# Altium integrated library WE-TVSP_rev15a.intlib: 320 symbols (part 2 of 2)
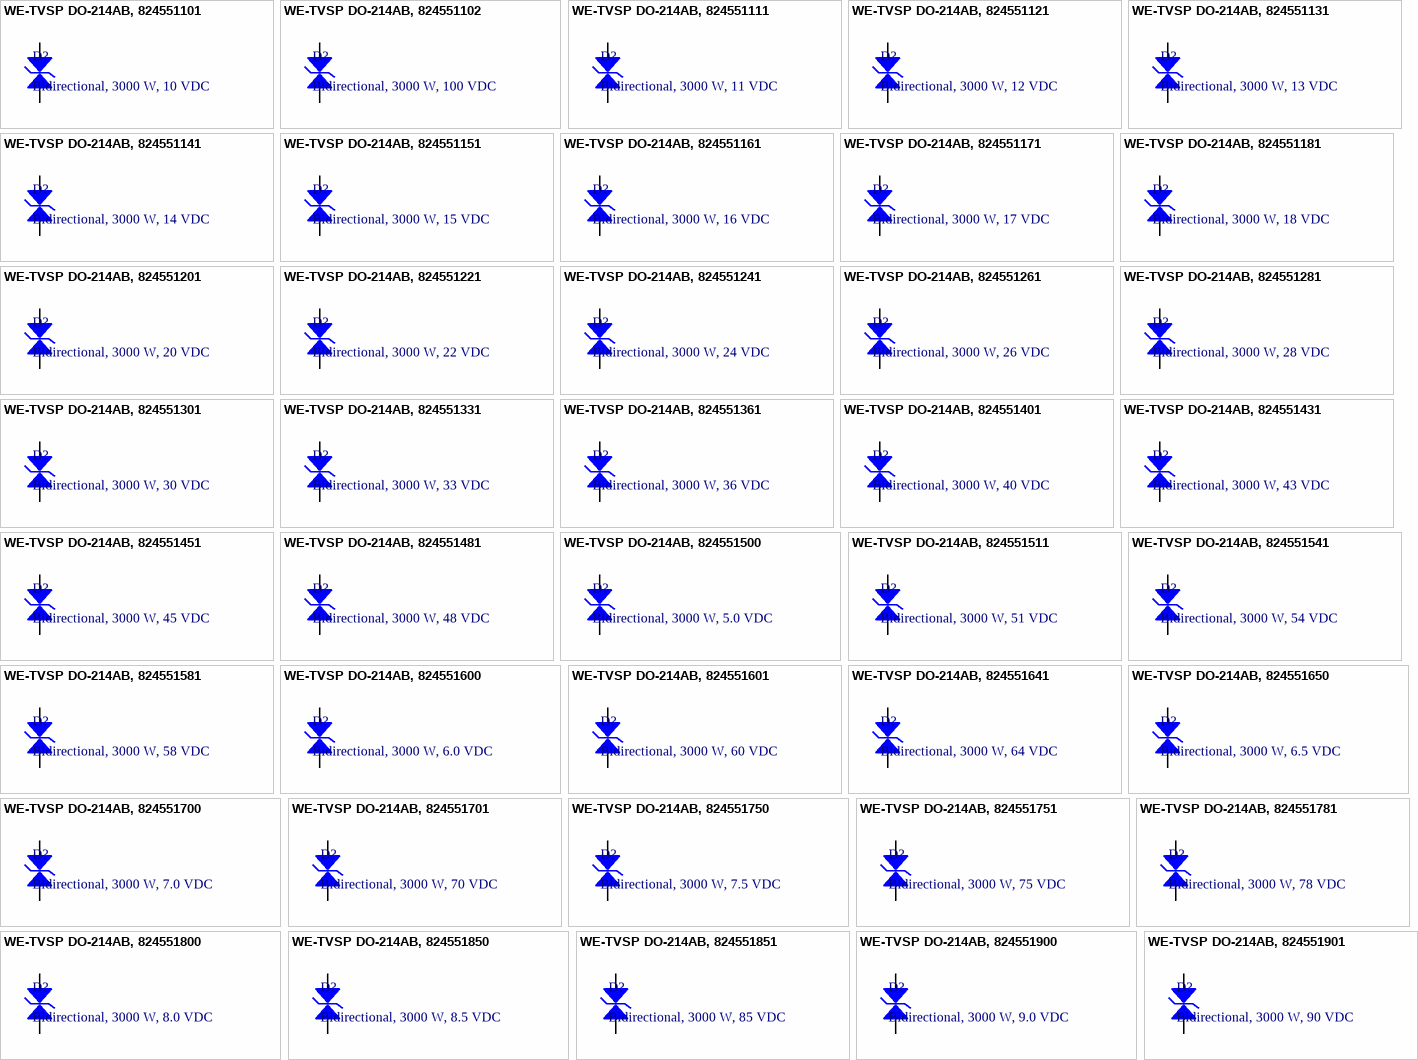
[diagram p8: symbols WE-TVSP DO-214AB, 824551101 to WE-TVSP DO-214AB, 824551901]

## WE-TVSP DO-214AB, 824551171
designator D?, comment Bidirectional, 3000 W, 17 VDC
WE-TVSP Power TVS Diode, bidirectional, 3000 W, 17 VDC; partNo: 824551171; Manufacturer: Wurth Elektronik
footprint DO-214AB_Bidirectional
pins: 1, 2

## WE-TVSP DO-214AB, 824551181
designator D?, comment Bidirectional, 3000 W, 18 VDC
WE-TVSP Power TVS Diode, bidirectional, 3000 W, 18 VDC; partNo: 824551181; Manufacturer: Wurth Elektronik
footprint DO-214AB_Bidirectional
pins: 1, 2

## WE-TVSP DO-214AB, 824551201
designator D?, comment Bidirectional, 3000 W, 20 VDC
WE-TVSP Power TVS Diode, bidirectional, 3000 W, 20 VDC; partNo: 824551201; Manufacturer: Wurth Elektronik
footprint DO-214AB_Bidirectional
pins: 1, 2

## WE-TVSP DO-214AB, 824551221
designator D?, comment Bidirectional, 3000 W, 22 VDC
WE-TVSP Power TVS Diode, bidirectional, 3000 W, 22 VDC; partNo: 824551221; Manufacturer: Wurth Elektronik
footprint DO-214AB_Bidirectional
pins: 1, 2

## WE-TVSP DO-214AB, 824551241
designator D?, comment Bidirectional, 3000 W, 24 VDC
WE-TVSP Power TVS Diode, bidirectional, 3000 W, 24 VDC; partNo: 824551241; Manufacturer: Wurth Elektronik
footprint DO-214AB_Bidirectional
pins: 1, 2

## WE-TVSP DO-214AB, 824551261
designator D?, comment Bidirectional, 3000 W, 26 VDC
WE-TVSP Power TVS Diode, bidirectional, 3000 W, 26 VDC; partNo: 824551261; Manufacturer: Wurth Elektronik
footprint DO-214AB_Bidirectional
pins: 1, 2

## WE-TVSP DO-214AB, 824551281
designator D?, comment Bidirectional, 3000 W, 28 VDC
WE-TVSP Power TVS Diode, bidirectional, 3000 W, 28 VDC; partNo: 824551281; Manufacturer: Wurth Elektronik
footprint DO-214AB_Bidirectional
pins: 1, 2

## WE-TVSP DO-214AB, 824551301
designator D?, comment Bidirectional, 3000 W, 30 VDC
WE-TVSP Power TVS Diode, bidirectional, 3000 W, 30 VDC; partNo: 824551301; Manufacturer: Wurth Elektronik
footprint DO-214AB_Bidirectional
pins: 1, 2

## WE-TVSP DO-214AB, 824551331
designator D?, comment Bidirectional, 3000 W, 33 VDC
WE-TVSP Power TVS Diode, bidirectional, 3000 W, 33 VDC; partNo: 824551331; Manufacturer: Wurth Elektronik
footprint DO-214AB_Bidirectional
pins: 1, 2

## WE-TVSP DO-214AB, 824551361
designator D?, comment Bidirectional, 3000 W, 36 VDC
WE-TVSP Power TVS Diode, bidirectional, 3000 W, 36 VDC; partNo: 824551361; Manufacturer: Wurth Elektronik
footprint DO-214AB_Bidirectional
pins: 1, 2

## WE-TVSP DO-214AB, 824551401
designator D?, comment Bidirectional, 3000 W, 40 VDC
WE-TVSP Power TVS Diode, bidirectional, 3000 W, 40 VDC; partNo: 824551401; Manufacturer: Wurth Elektronik
footprint DO-214AB_Bidirectional
pins: 1, 2

## WE-TVSP DO-214AB, 824551431
designator D?, comment Bidirectional, 3000 W, 43 VDC
WE-TVSP Power TVS Diode, bidirectional, 3000 W, 43 VDC; partNo: 824551431; Manufacturer: Wurth Elektronik
footprint DO-214AB_Bidirectional
pins: 1, 2

## WE-TVSP DO-214AB, 824551451
designator D?, comment Bidirectional, 3000 W, 45 VDC
WE-TVSP Power TVS Diode, bidirectional, 3000 W, 45 VDC; partNo: 824551451; Manufacturer: Wurth Elektronik
footprint DO-214AB_Bidirectional
pins: 1, 2

## WE-TVSP DO-214AB, 824551481
designator D?, comment Bidirectional, 3000 W, 48 VDC
WE-TVSP Power TVS Diode, bidirectional, 3000 W, 48 VDC; partNo: 824551481; Manufacturer: Wurth Elektronik
footprint DO-214AB_Bidirectional
pins: 1, 2

## WE-TVSP DO-214AB, 824551500
designator D?, comment Bidirectional, 3000 W, 5.0 VDC
WE-TVSP Power TVS Diode, bidirectional, 3000 W, 5.0 VDC; partNo: 824551500; Manufacturer: Wurth Elektronik
footprint DO-214AB_Bidirectional
pins: 1, 2

## WE-TVSP DO-214AB, 824551511
designator D?, comment Bidirectional, 3000 W, 51 VDC
WE-TVSP Power TVS Diode, bidirectional, 3000 W, 51 VDC; partNo: 824551511; Manufacturer: Wurth Elektronik
footprint DO-214AB_Bidirectional
pins: 1, 2

## WE-TVSP DO-214AB, 824551541
designator D?, comment Bidirectional, 3000 W, 54 VDC
WE-TVSP Power TVS Diode, bidirectional, 3000 W, 54 VDC; partNo: 824551541; Manufacturer: Wurth Elektronik
footprint DO-214AB_Bidirectional
pins: 1, 2

## WE-TVSP DO-214AB, 824551581
designator D?, comment Bidirectional, 3000 W, 58 VDC
WE-TVSP Power TVS Diode, bidirectional, 3000 W, 58 VDC; partNo: 824551581; Manufacturer: Wurth Elektronik
footprint DO-214AB_Bidirectional
pins: 1, 2

## WE-TVSP DO-214AB, 824551600
designator D?, comment Bidirectional, 3000 W, 6.0 VDC
WE-TVSP Power TVS Diode, bidirectional, 3000 W, 6.0 VDC; partNo: 824551600; Manufacturer: Wurth Elektronik
footprint DO-214AB_Bidirectional
pins: 1, 2

## WE-TVSP DO-214AB, 824551601
designator D?, comment Bidirectional, 3000 W, 60 VDC
WE-TVSP Power TVS Diode, bidirectional, 3000 W, 60 VDC; partNo: 824551601; Manufacturer: Wurth Elektronik
footprint DO-214AB_Bidirectional
pins: 1, 2

## WE-TVSP DO-214AB, 824551641
designator D?, comment Bidirectional, 3000 W, 64 VDC
WE-TVSP Power TVS Diode, bidirectional, 3000 W, 64 VDC; partNo: 824551641; Manufacturer: Wurth Elektronik
footprint DO-214AB_Bidirectional
pins: 1, 2

## WE-TVSP DO-214AB, 824551650
designator D?, comment Bidirectional, 3000 W, 6.5 VDC
WE-TVSP Power TVS Diode, bidirectional, 3000 W, 6.5 VDC; partNo: 824551650; Manufacturer: Wurth Elektronik
footprint DO-214AB_Bidirectional
pins: 1, 2

## WE-TVSP DO-214AB, 824551700
designator D?, comment Bidirectional, 3000 W, 7.0 VDC
WE-TVSP Power TVS Diode, bidirectional, 3000 W, 7.0 VDC; partNo: 824551700; Manufacturer: Wurth Elektronik
footprint DO-214AB_Bidirectional
pins: 1, 2

## WE-TVSP DO-214AB, 824551701
designator D?, comment Bidirectional, 3000 W, 70 VDC
WE-TVSP Power TVS Diode, bidirectional, 3000 W, 70 VDC; partNo: 824551701; Manufacturer: Wurth Elektronik
footprint DO-214AB_Bidirectional
pins: 1, 2

## WE-TVSP DO-214AB, 824551750
designator D?, comment Bidirectional, 3000 W, 7.5 VDC
WE-TVSP Power TVS Diode, bidirectional, 3000 W, 7.5 VDC; partNo: 824551750; Manufacturer: Wurth Elektronik
footprint DO-214AB_Bidirectional
pins: 1, 2

## WE-TVSP DO-214AB, 824551751
designator D?, comment Bidirectional, 3000 W, 75 VDC
WE-TVSP Power TVS Diode, bidirectional, 3000 W, 75 VDC; partNo: 824551751; Manufacturer: Wurth Elektronik
footprint DO-214AB_Bidirectional
pins: 1, 2

## WE-TVSP DO-214AB, 824551781
designator D?, comment Bidirectional, 3000 W, 78 VDC
WE-TVSP Power TVS Diode, bidirectional, 3000 W, 78 VDC; partNo: 824551781; Manufacturer: Wurth Elektronik
footprint DO-214AB_Bidirectional
pins: 1, 2

## WE-TVSP DO-214AB, 824551800
designator D?, comment Bidirectional, 3000 W, 8.0 VDC
WE-TVSP Power TVS Diode, bidirectional, 3000 W, 8.0 VDC; partNo: 824551800; Manufacturer: Wurth Elektronik
footprint DO-214AB_Bidirectional
pins: 1, 2

## WE-TVSP DO-214AB, 824551850
designator D?, comment Bidirectional, 3000 W, 8.5 VDC
WE-TVSP Power TVS Diode, bidirectional, 3000 W, 8.5 VDC; partNo: 824551850; Manufacturer: Wurth Elektronik
footprint DO-214AB_Bidirectional
pins: 1, 2

## WE-TVSP DO-214AB, 824551851
designator D?, comment Bidirectional, 3000 W, 85 VDC
WE-TVSP Power TVS Diode, bidirectional, 3000 W, 85 VDC; partNo: 824551851; Manufacturer: Wurth Elektronik
footprint DO-214AB_Bidirectional
pins: 1, 2

## WE-TVSP DO-214AB, 824551900
designator D?, comment Bidirectional, 3000 W, 9.0 VDC
WE-TVSP Power TVS Diode, bidirectional, 3000 W, 9.0 VDC; partNo: 824551900; Manufacturer: Wurth Elektronik
footprint DO-214AB_Bidirectional
pins: 1, 2

## WE-TVSP DO-214AB, 824551901
designator D?, comment Bidirectional, 3000 W, 90 VDC
WE-TVSP Power TVS Diode, bidirectional, 3000 W, 90 VDC; partNo: 824551901; Manufacturer: Wurth Elektronik
footprint DO-214AB_Bidirectional
pins: 1, 2


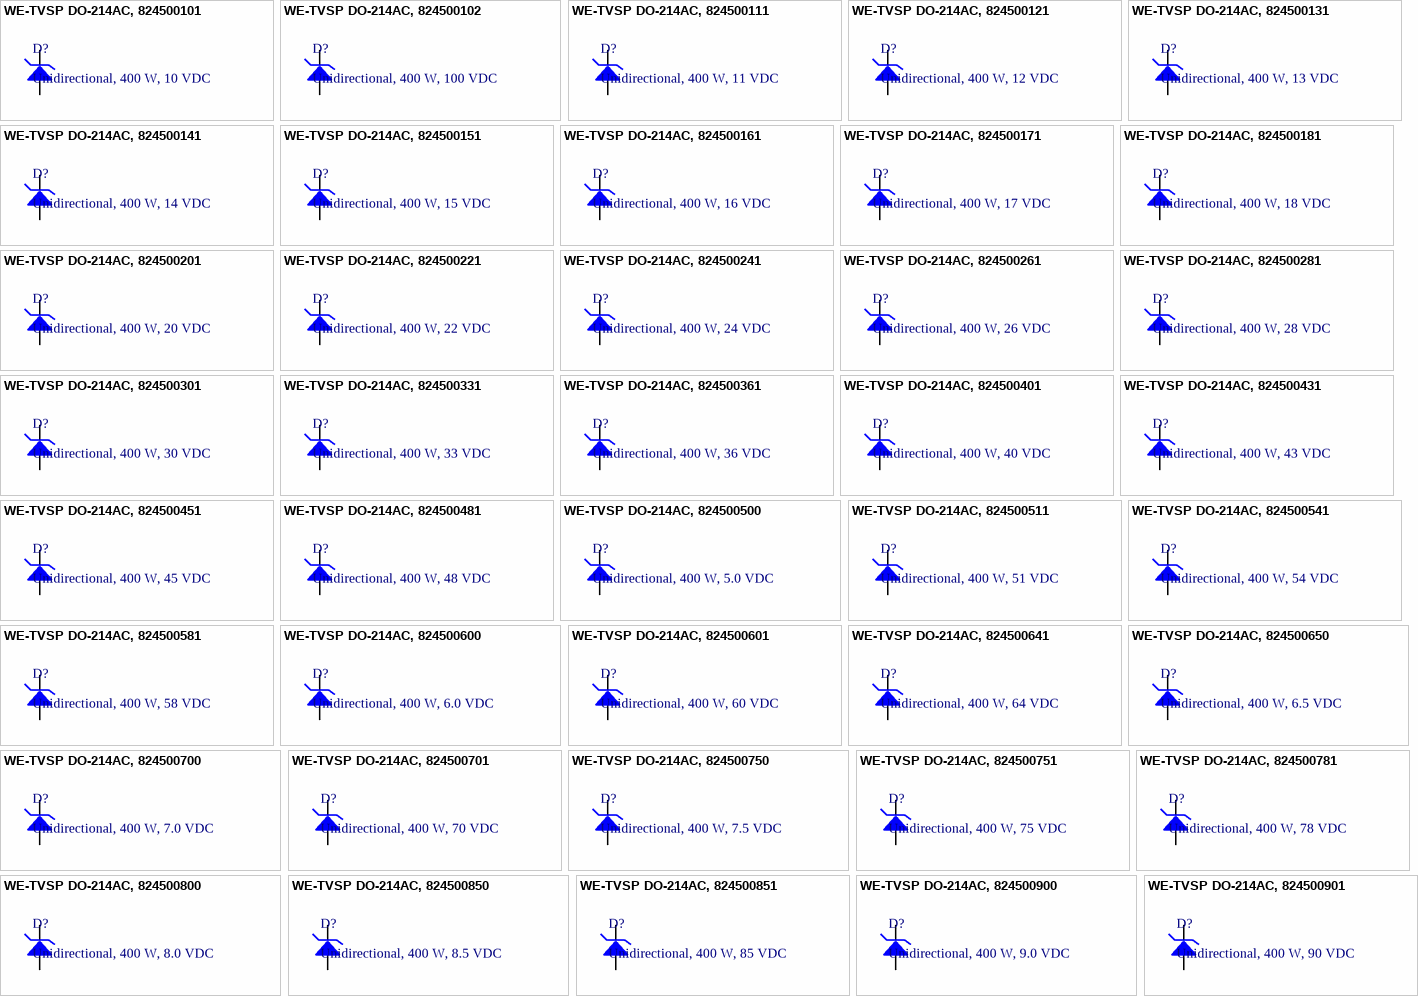
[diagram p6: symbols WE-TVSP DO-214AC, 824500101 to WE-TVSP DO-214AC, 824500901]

## WE-TVSP DO-214AC, 824500101
designator D?, comment Unidirectional, 400 W, 10 VDC
WE-TVSP Power TVS Diode, Unidirectional, 400 W, 10 VDC; partNo: 824500101; Manufacturer: Wurth Elektronik
footprint DO-214AC_Unidirectional
pins: 1, 2

## WE-TVSP DO-214AC, 824500102
designator D?, comment Unidirectional, 400 W, 100 VDC
WE-TVSP Power TVS Diode, Unidirectional, 400 W, 100 VDC; partNo: 824500102; Manufacturer: Wurth Elektronik
footprint DO-214AC_Unidirectional
pins: 1, 2

## WE-TVSP DO-214AC, 824500111
designator D?, comment Unidirectional, 400 W, 11 VDC
WE-TVSP Power TVS Diode, Unidirectional, 400 W, 11 VDC; partNo: 824500111; Manufacturer: Wurth Elektronik
footprint DO-214AC_Unidirectional
pins: 1, 2

## WE-TVSP DO-214AC, 824500121
designator D?, comment Unidirectional, 400 W, 12 VDC
WE-TVSP Power TVS Diode, Unidirectional, 400 W, 12 VDC; partNo: 824500121; Manufacturer: Wurth Elektronik
footprint DO-214AC_Unidirectional
pins: 1, 2

## WE-TVSP DO-214AC, 824500131
designator D?, comment Unidirectional, 400 W, 13 VDC
WE-TVSP Power TVS Diode, Unidirectional, 400 W, 13 VDC; partNo: 824500131; Manufacturer: Wurth Elektronik
footprint DO-214AC_Unidirectional
pins: 1, 2

## WE-TVSP DO-214AC, 824500141
designator D?, comment Unidirectional, 400 W, 14 VDC
WE-TVSP Power TVS Diode, Unidirectional, 400 W, 14 VDC; partNo: 824500141; Manufacturer: Wurth Elektronik
footprint DO-214AC_Unidirectional
pins: 1, 2

## WE-TVSP DO-214AC, 824500151
designator D?, comment Unidirectional, 400 W, 15 VDC
WE-TVSP Power TVS Diode, Unidirectional, 400 W, 15 VDC; partNo: 824500151; Manufacturer: Wurth Elektronik
footprint DO-214AC_Unidirectional
pins: 1, 2

## WE-TVSP DO-214AC, 824500161
designator D?, comment Unidirectional, 400 W, 16 VDC
WE-TVSP Power TVS Diode, Unidirectional, 400 W, 16 VDC; partNo: 824500161; Manufacturer: Wurth Elektronik
footprint DO-214AC_Unidirectional
pins: 1, 2

## WE-TVSP DO-214AC, 824500171
designator D?, comment Unidirectional, 400 W, 17 VDC
WE-TVSP Power TVS Diode, Unidirectional, 400 W, 17 VDC; partNo: 824500171; Manufacturer: Wurth Elektronik
footprint DO-214AC_Unidirectional
pins: 1, 2

## WE-TVSP DO-214AC, 824500181
designator D?, comment Unidirectional, 400 W, 18 VDC
WE-TVSP Power TVS Diode, Unidirectional, 400 W, 18 VDC; partNo: 824500181; Manufacturer: Wurth Elektronik
footprint DO-214AC_Unidirectional
pins: 1, 2

## WE-TVSP DO-214AC, 824500201
designator D?, comment Unidirectional, 400 W, 20 VDC
WE-TVSP Power TVS Diode, Unidirectional, 400 W, 20 VDC; partNo: 824500201; Manufacturer: Wurth Elektronik
footprint DO-214AC_Unidirectional
pins: 1, 2

## WE-TVSP DO-214AC, 824500221
designator D?, comment Unidirectional, 400 W, 22 VDC
WE-TVSP Power TVS Diode, Unidirectional, 400 W, 22 VDC; partNo: 824500221; Manufacturer: Wurth Elektronik
footprint DO-214AC_Unidirectional
pins: 1, 2

## WE-TVSP DO-214AC, 824500241
designator D?, comment Unidirectional, 400 W, 24 VDC
WE-TVSP Power TVS Diode, Unidirectional, 400 W, 24 VDC; partNo: 824500241; Manufacturer: Wurth Elektronik
footprint DO-214AC_Unidirectional
pins: 1, 2

## WE-TVSP DO-214AC, 824500261
designator D?, comment Unidirectional, 400 W, 26 VDC
WE-TVSP Power TVS Diode, Unidirectional, 400 W, 26 VDC; partNo: 824500261; Manufacturer: Wurth Elektronik
footprint DO-214AC_Unidirectional
pins: 1, 2

## WE-TVSP DO-214AC, 824500281
designator D?, comment Unidirectional, 400 W, 28 VDC
WE-TVSP Power TVS Diode, Unidirectional, 400 W, 28 VDC; partNo: 824500281; Manufacturer: Wurth Elektronik
footprint DO-214AC_Unidirectional
pins: 1, 2

## WE-TVSP DO-214AC, 824500301
designator D?, comment Unidirectional, 400 W, 30 VDC
WE-TVSP Power TVS Diode, Unidirectional, 400 W, 30 VDC; partNo: 824500301; Manufacturer: Wurth Elektronik
footprint DO-214AC_Unidirectional
pins: 1, 2

## WE-TVSP DO-214AC, 824500331
designator D?, comment Unidirectional, 400 W, 33 VDC
WE-TVSP Power TVS Diode, Unidirectional, 400 W, 33 VDC; partNo: 824500331; Manufacturer: Wurth Elektronik
footprint DO-214AC_Unidirectional
pins: 1, 2

## WE-TVSP DO-214AC, 824500361
designator D?, comment Unidirectional, 400 W, 36 VDC
WE-TVSP Power TVS Diode, Unidirectional, 400 W, 36 VDC; partNo: 824500361; Manufacturer: Wurth Elektronik
footprint DO-214AC_Unidirectional
pins: 1, 2

## WE-TVSP DO-214AC, 824500401
designator D?, comment Unidirectional, 400 W, 40 VDC
WE-TVSP Power TVS Diode, Unidirectional, 400 W, 40 VDC; partNo: 824500401; Manufacturer: Wurth Elektronik
footprint DO-214AC_Unidirectional
pins: 1, 2

## WE-TVSP DO-214AC, 824500431
designator D?, comment Unidirectional, 400 W, 43 VDC
WE-TVSP Power TVS Diode, Unidirectional, 400 W, 43 VDC; partNo: 824500431; Manufacturer: Wurth Elektronik
footprint DO-214AC_Unidirectional
pins: 1, 2

## WE-TVSP DO-214AC, 824500451
designator D?, comment Unidirectional, 400 W, 45 VDC
WE-TVSP Power TVS Diode, Unidirectional, 400 W, 45 VDC; partNo: 824500451; Manufacturer: Wurth Elektronik
footprint DO-214AC_Unidirectional
pins: 1, 2

## WE-TVSP DO-214AC, 824500481
designator D?, comment Unidirectional, 400 W, 48 VDC
WE-TVSP Power TVS Diode, Unidirectional, 400 W, 48 VDC; partNo: 824500481; Manufacturer: Wurth Elektronik
footprint DO-214AC_Unidirectional
pins: 1, 2

## WE-TVSP DO-214AC, 824500500
designator D?, comment Unidirectional, 400 W, 5.0 VDC
WE-TVSP Power TVS Diode, Unidirectional, 400 W, 5.0 VDC; partNo: 824500500; Manufacturer: Wurth Elektronik
footprint DO-214AC_Unidirectional
pins: 1, 2

## WE-TVSP DO-214AC, 824500511
designator D?, comment Unidirectional, 400 W, 51 VDC
WE-TVSP Power TVS Diode, Unidirectional, 400 W, 51 VDC; partNo: 824500511; Manufacturer: Wurth Elektronik
footprint DO-214AC_Unidirectional
pins: 1, 2

## WE-TVSP DO-214AC, 824500541
designator D?, comment Unidirectional, 400 W, 54 VDC
WE-TVSP Power TVS Diode, Unidirectional, 400 W, 54 VDC; partNo: 824500541; Manufacturer: Wurth Elektronik
footprint DO-214AC_Unidirectional
pins: 1, 2

## WE-TVSP DO-214AC, 824500581
designator D?, comment Unidirectional, 400 W, 58 VDC
WE-TVSP Power TVS Diode, Unidirectional, 400 W, 58 VDC; partNo: 824500581; Manufacturer: Wurth Elektronik
footprint DO-214AC_Unidirectional
pins: 1, 2

## WE-TVSP DO-214AC, 824500600
designator D?, comment Unidirectional, 400 W, 6.0 VDC
WE-TVSP Power TVS Diode, Unidirectional, 400 W, 6.0 VDC; partNo: 824500600; Manufacturer: Wurth Elektronik
footprint DO-214AC_Unidirectional
pins: 1, 2

## WE-TVSP DO-214AC, 824500601
designator D?, comment Unidirectional, 400 W, 60 VDC
WE-TVSP Power TVS Diode, Unidirectional, 400 W, 60 VDC; partNo: 824500601; Manufacturer: Wurth Elektronik
footprint DO-214AC_Unidirectional
pins: 1, 2

## WE-TVSP DO-214AC, 824500641
designator D?, comment Unidirectional, 400 W, 64 VDC
WE-TVSP Power TVS Diode, Unidirectional, 400 W, 64 VDC; partNo: 824500641; Manufacturer: Wurth Elektronik
footprint DO-214AC_Unidirectional
pins: 1, 2

## WE-TVSP DO-214AC, 824500650
designator D?, comment Unidirectional, 400 W, 6.5 VDC
WE-TVSP Power TVS Diode, Unidirectional, 400 W, 6.5 VDC; partNo: 824500650; Manufacturer: Wurth Elektronik
footprint DO-214AC_Unidirectional
pins: 1, 2

## WE-TVSP DO-214AC, 824500700
designator D?, comment Unidirectional, 400 W, 7.0 VDC
WE-TVSP Power TVS Diode, Unidirectional, 400 W, 7.0 VDC; partNo: 824500700; Manufacturer: Wurth Elektronik
footprint DO-214AC_Unidirectional
pins: 1, 2

## WE-TVSP DO-214AC, 824500701
designator D?, comment Unidirectional, 400 W, 70 VDC
WE-TVSP Power TVS Diode, Unidirectional, 400 W, 70 VDC; partNo: 824500701; Manufacturer: Wurth Elektronik
footprint DO-214AC_Unidirectional
pins: 1, 2

## WE-TVSP DO-214AC, 824500750
designator D?, comment Unidirectional, 400 W, 7.5 VDC
WE-TVSP Power TVS Diode, Unidirectional, 400 W, 7.5 VDC; partNo: 824500750; Manufacturer: Wurth Elektronik
footprint DO-214AC_Unidirectional
pins: 1, 2

## WE-TVSP DO-214AC, 824500751
designator D?, comment Unidirectional, 400 W, 75 VDC
WE-TVSP Power TVS Diode, Unidirectional, 400 W, 75 VDC; partNo: 824500751; Manufacturer: Wurth Elektronik
footprint DO-214AC_Unidirectional
pins: 1, 2

## WE-TVSP DO-214AC, 824500781
designator D?, comment Unidirectional, 400 W, 78 VDC
WE-TVSP Power TVS Diode, Unidirectional, 400 W, 78 VDC; partNo: 824500781; Manufacturer: Wurth Elektronik
footprint DO-214AC_Unidirectional
pins: 1, 2

## WE-TVSP DO-214AC, 824500800
designator D?, comment Unidirectional, 400 W, 8.0 VDC
WE-TVSP Power TVS Diode, Unidirectional, 400 W, 8.0 VDC; partNo: 824500800; Manufacturer: Wurth Elektronik
footprint DO-214AC_Unidirectional
pins: 1, 2

## WE-TVSP DO-214AC, 824500850
designator D?, comment Unidirectional, 400 W, 8.5 VDC
WE-TVSP Power TVS Diode, Unidirectional, 400 W, 8.5 VDC; partNo: 824500850; Manufacturer: Wurth Elektronik
footprint DO-214AC_Unidirectional
pins: 1, 2

## WE-TVSP DO-214AC, 824500851
designator D?, comment Unidirectional, 400 W, 85 VDC
WE-TVSP Power TVS Diode, Unidirectional, 400 W, 85 VDC; partNo: 824500851; Manufacturer: Wurth Elektronik
footprint DO-214AC_Unidirectional
pins: 1, 2

## WE-TVSP DO-214AC, 824500900
designator D?, comment Unidirectional, 400 W, 9.0 VDC
WE-TVSP Power TVS Diode, Unidirectional, 400 W, 9.0 VDC; partNo: 824500900; Manufacturer: Wurth Elektronik
footprint DO-214AC_Unidirectional
pins: 1, 2

## WE-TVSP DO-214AC, 824500901
designator D?, comment Unidirectional, 400 W, 90 VDC
WE-TVSP Power TVS Diode, Unidirectional, 400 W, 90 VDC; partNo: 824500901; Manufacturer: Wurth Elektronik
footprint DO-214AC_Unidirectional
pins: 1, 2


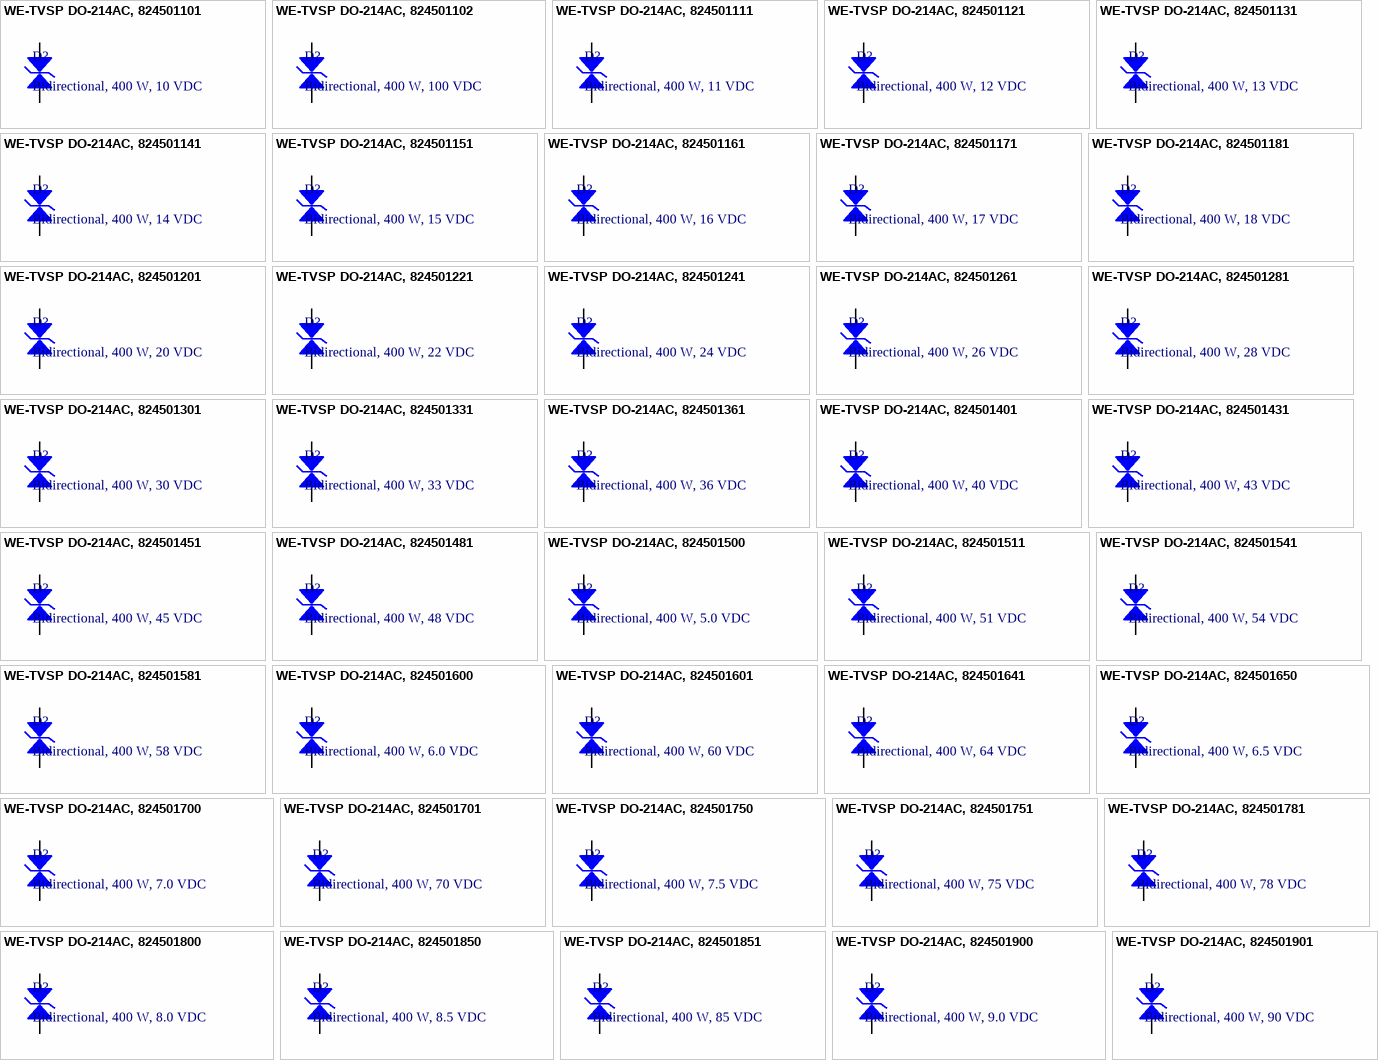
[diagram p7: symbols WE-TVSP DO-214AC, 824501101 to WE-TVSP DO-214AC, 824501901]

## WE-TVSP DO-214AC, 824501101
designator D?, comment Bidirectional, 400 W, 10 VDC
WE-TVSP Power TVS Diode, bidirectional, 400 W, 10 VDC; partNo: 824501101; Manufacturer: Wurth Elektronik
footprint DO-214AC_Bidirectional
pins: 1, 2

## WE-TVSP DO-214AC, 824501102
designator D?, comment Bidirectional, 400 W, 100 VDC
WE-TVSP Power TVS Diode, bidirectional, 400 W, 100 VDC; partNo: 824501102; Manufacturer: Wurth Elektronik
footprint DO-214AC_Bidirectional
pins: 1, 2

## WE-TVSP DO-214AC, 824501111
designator D?, comment Bidirectional, 400 W, 11 VDC
WE-TVSP Power TVS Diode, bidirectional, 400 W, 11 VDC; partNo: 824501111; Manufacturer: Wurth Elektronik
footprint DO-214AC_Bidirectional
pins: 1, 2

## WE-TVSP DO-214AC, 824501121
designator D?, comment Bidirectional, 400 W, 12 VDC
WE-TVSP Power TVS Diode, bidirectional, 400 W, 12 VDC; partNo: 824501121; Manufacturer: Wurth Elektronik
footprint DO-214AC_Bidirectional
pins: 1, 2

## WE-TVSP DO-214AC, 824501131
designator D?, comment Bidirectional, 400 W, 13 VDC
WE-TVSP Power TVS Diode, bidirectional, 400 W, 13 VDC; partNo: 824501131; Manufacturer: Wurth Elektronik
footprint DO-214AC_Bidirectional
pins: 1, 2

## WE-TVSP DO-214AC, 824501141
designator D?, comment Bidirectional, 400 W, 14 VDC
WE-TVSP Power TVS Diode, bidirectional, 400 W, 14 VDC; partNo: 824501141; Manufacturer: Wurth Elektronik
footprint DO-214AC_Bidirectional
pins: 1, 2

## WE-TVSP DO-214AC, 824501151
designator D?, comment Bidirectional, 400 W, 15 VDC
WE-TVSP Power TVS Diode, bidirectional, 400 W, 15 VDC; partNo: 824501151; Manufacturer: Wurth Elektronik
footprint DO-214AC_Bidirectional
pins: 1, 2

## WE-TVSP DO-214AC, 824501161
designator D?, comment Bidirectional, 400 W, 16 VDC
WE-TVSP Power TVS Diode, bidirectional, 400 W, 16 VDC; partNo: 824501161; Manufacturer: Wurth Elektronik
footprint DO-214AC_Bidirectional
pins: 1, 2

## WE-TVSP DO-214AC, 824501171
designator D?, comment Bidirectional, 400 W, 17 VDC
WE-TVSP Power TVS Diode, bidirectional, 400 W, 17 VDC; partNo: 824501171; Manufacturer: Wurth Elektronik
footprint DO-214AC_Bidirectional
pins: 1, 2

## WE-TVSP DO-214AC, 824501181
designator D?, comment Bidirectional, 400 W, 18 VDC
WE-TVSP Power TVS Diode, bidirectional, 400 W, 18 VDC; partNo: 824501181; Manufacturer: Wurth Elektronik
footprint DO-214AC_Bidirectional
pins: 1, 2

## WE-TVSP DO-214AC, 824501201
designator D?, comment Bidirectional, 400 W, 20 VDC
WE-TVSP Power TVS Diode, bidirectional, 400 W, 20 VDC; partNo: 824501201; Manufacturer: Wurth Elektronik
footprint DO-214AC_Bidirectional
pins: 1, 2

## WE-TVSP DO-214AC, 824501221
designator D?, comment Bidirectional, 400 W, 22 VDC
WE-TVSP Power TVS Diode, bidirectional, 400 W, 22 VDC; partNo: 824501221; Manufacturer: Wurth Elektronik
footprint DO-214AC_Bidirectional
pins: 1, 2

## WE-TVSP DO-214AC, 824501241
designator D?, comment Bidirectional, 400 W, 24 VDC
WE-TVSP Power TVS Diode, bidirectional, 400 W, 24 VDC; partNo: 824501241; Manufacturer: Wurth Elektronik
footprint DO-214AC_Bidirectional
pins: 1, 2

## WE-TVSP DO-214AC, 824501261
designator D?, comment Bidirectional, 400 W, 26 VDC
WE-TVSP Power TVS Diode, bidirectional, 400 W, 26 VDC; partNo: 824501261; Manufacturer: Wurth Elektronik
footprint DO-214AC_Bidirectional
pins: 1, 2

## WE-TVSP DO-214AC, 824501281
designator D?, comment Bidirectional, 400 W, 28 VDC
WE-TVSP Power TVS Diode, bidirectional, 400 W, 28 VDC; partNo: 824501281; Manufacturer: Wurth Elektronik
footprint DO-214AC_Bidirectional
pins: 1, 2

## WE-TVSP DO-214AC, 824501301
designator D?, comment Bidirectional, 400 W, 30 VDC
WE-TVSP Power TVS Diode, bidirectional, 400 W, 30 VDC; partNo: 824501301; Manufacturer: Wurth Elektronik
footprint DO-214AC_Bidirectional
pins: 1, 2

## WE-TVSP DO-214AC, 824501331
designator D?, comment Bidirectional, 400 W, 33 VDC
WE-TVSP Power TVS Diode, bidirectional, 400 W, 33 VDC; partNo: 824501331; Manufacturer: Wurth Elektronik
footprint DO-214AC_Bidirectional
pins: 1, 2

## WE-TVSP DO-214AC, 824501361
designator D?, comment Bidirectional, 400 W, 36 VDC
WE-TVSP Power TVS Diode, bidirectional, 400 W, 36 VDC; partNo: 824501361; Manufacturer: Wurth Elektronik
footprint DO-214AC_Bidirectional
pins: 1, 2

## WE-TVSP DO-214AC, 824501401
designator D?, comment Bidirectional, 400 W, 40 VDC
WE-TVSP Power TVS Diode, bidirectional, 400 W, 40 VDC; partNo: 824501401; Manufacturer: Wurth Elektronik
footprint DO-214AC_Bidirectional
pins: 1, 2

## WE-TVSP DO-214AC, 824501431
designator D?, comment Bidirectional, 400 W, 43 VDC
WE-TVSP Power TVS Diode, bidirectional, 400 W, 43 VDC; partNo: 824501431; Manufacturer: Wurth Elektronik
footprint DO-214AC_Bidirectional
pins: 1, 2

## WE-TVSP DO-214AC, 824501451
designator D?, comment Bidirectional, 400 W, 45 VDC
WE-TVSP Power TVS Diode, bidirectional, 400 W, 45 VDC; partNo: 824501451; Manufacturer: Wurth Elektronik
footprint DO-214AC_Bidirectional
pins: 1, 2

## WE-TVSP DO-214AC, 824501481
designator D?, comment Bidirectional, 400 W, 48 VDC
WE-TVSP Power TVS Diode, bidirectional, 400 W, 48 VDC; partNo: 824501481; Manufacturer: Wurth Elektronik
footprint DO-214AC_Bidirectional
pins: 1, 2

## WE-TVSP DO-214AC, 824501500
designator D?, comment Bidirectional, 400 W, 5.0 VDC
WE-TVSP Power TVS Diode, bidirectional, 400 W, 5.0 VDC; partNo: 824501500; Manufacturer: Wurth Elektronik
footprint DO-214AC_Bidirectional
pins: 1, 2

## WE-TVSP DO-214AC, 824501511
designator D?, comment Bidirectional, 400 W, 51 VDC
WE-TVSP Power TVS Diode, bidirectional, 400 W, 51 VDC; partNo: 824501511; Manufacturer: Wurth Elektronik
footprint DO-214AC_Bidirectional
pins: 1, 2

## WE-TVSP DO-214AC, 824501541
designator D?, comment Bidirectional, 400 W, 54 VDC
WE-TVSP Power TVS Diode, bidirectional, 400 W, 54 VDC; partNo: 824501541; Manufacturer: Wurth Elektronik
footprint DO-214AC_Bidirectional
pins: 1, 2

## WE-TVSP DO-214AC, 824501581
designator D?, comment Bidirectional, 400 W, 58 VDC
WE-TVSP Power TVS Diode, bidirectional, 400 W, 58 VDC; partNo: 824501581; Manufacturer: Wurth Elektronik
footprint DO-214AC_Bidirectional
pins: 1, 2

## WE-TVSP DO-214AC, 824501600
designator D?, comment Bidirectional, 400 W, 6.0 VDC
WE-TVSP Power TVS Diode, bidirectional, 400 W, 6.0 VDC; partNo: 824501600; Manufacturer: Wurth Elektronik
footprint DO-214AC_Bidirectional
pins: 1, 2

## WE-TVSP DO-214AC, 824501601
designator D?, comment Bidirectional, 400 W, 60 VDC
WE-TVSP Power TVS Diode, bidirectional, 400 W, 60 VDC; partNo: 824501601; Manufacturer: Wurth Elektronik
footprint DO-214AC_Bidirectional
pins: 1, 2

## WE-TVSP DO-214AC, 824501641
designator D?, comment Bidirectional, 400 W, 64 VDC
WE-TVSP Power TVS Diode, bidirectional, 400 W, 64 VDC; partNo: 824501641; Manufacturer: Wurth Elektronik
footprint DO-214AC_Bidirectional
pins: 1, 2

## WE-TVSP DO-214AC, 824501650
designator D?, comment Bidirectional, 400 W, 6.5 VDC
WE-TVSP Power TVS Diode, bidirectional, 400 W, 6.5 VDC; partNo: 824501650; Manufacturer: Wurth Elektronik
footprint DO-214AC_Bidirectional
pins: 1, 2

## WE-TVSP DO-214AC, 824501700
designator D?, comment Bidirectional, 400 W, 7.0 VDC
WE-TVSP Power TVS Diode, bidirectional, 400 W, 7.0 VDC; partNo: 824501700; Manufacturer: Wurth Elektronik
footprint DO-214AC_Bidirectional
pins: 1, 2

## WE-TVSP DO-214AC, 824501701
designator D?, comment Bidirectional, 400 W, 70 VDC
WE-TVSP Power TVS Diode, bidirectional, 400 W, 70 VDC; partNo: 824501701; Manufacturer: Wurth Elektronik
footprint DO-214AC_Bidirectional
pins: 1, 2

## WE-TVSP DO-214AC, 824501750
designator D?, comment Bidirectional, 400 W, 7.5 VDC
WE-TVSP Power TVS Diode, bidirectional, 400 W, 7.5 VDC; partNo: 824501750; Manufacturer: Wurth Elektronik
footprint DO-214AC_Bidirectional
pins: 1, 2

## WE-TVSP DO-214AC, 824501751
designator D?, comment Bidirectional, 400 W, 75 VDC
WE-TVSP Power TVS Diode, bidirectional, 400 W, 75 VDC; partNo: 824501751; Manufacturer: Wurth Elektronik
footprint DO-214AC_Bidirectional
pins: 1, 2

## WE-TVSP DO-214AC, 824501781
designator D?, comment Bidirectional, 400 W, 78 VDC
WE-TVSP Power TVS Diode, bidirectional, 400 W, 78 VDC; partNo: 824501781; Manufacturer: Wurth Elektronik
footprint DO-214AC_Bidirectional
pins: 1, 2

## WE-TVSP DO-214AC, 824501800
designator D?, comment Bidirectional, 400 W, 8.0 VDC
WE-TVSP Power TVS Diode, bidirectional, 400 W, 8.0 VDC; partNo: 824501800; Manufacturer: Wurth Elektronik
footprint DO-214AC_Bidirectional
pins: 1, 2

## WE-TVSP DO-214AC, 824501850
designator D?, comment Bidirectional, 400 W, 8.5 VDC
WE-TVSP Power TVS Diode, bidirectional, 400 W, 8.5 VDC; partNo: 824501850; Manufacturer: Wurth Elektronik
footprint DO-214AC_Bidirectional
pins: 1, 2

## WE-TVSP DO-214AC, 824501851
designator D?, comment Bidirectional, 400 W, 85 VDC
WE-TVSP Power TVS Diode, bidirectional, 400 W, 85 VDC; partNo: 824501851; Manufacturer: Wurth Elektronik
footprint DO-214AC_Bidirectional
pins: 1, 2

## WE-TVSP DO-214AC, 824501900
designator D?, comment Bidirectional, 400 W, 9.0 VDC
WE-TVSP Power TVS Diode, bidirectional, 400 W, 9.0 VDC; partNo: 824501900; Manufacturer: Wurth Elektronik
footprint DO-214AC_Bidirectional
pins: 1, 2

## WE-TVSP DO-214AC, 824501901
designator D?, comment Bidirectional, 400 W, 90 VDC
WE-TVSP Power TVS Diode, bidirectional, 400 W, 90 VDC; partNo: 824501901; Manufacturer: Wurth Elektronik
footprint DO-214AC_Bidirectional
pins: 1, 2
